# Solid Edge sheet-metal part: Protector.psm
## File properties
Title: Protector
Author: windows
Template: Iso Metric Sheet Metal.psm
Last saved by: windows
Revision: 4
Application: Solid Edge
Username: windows
Density: 2712,000 kg/m^3
Accuracy: 0,990
Material Thickness: 1,00 mm
Bend Radius: 1,00 mm
Relief Width: 1,00 mm
Relief Length: 0,00 mm
Neutral Factor: 0,330
Minimum Arc Length: 0,10 mm
Deviational Tolerance: 0,10 mm
Material: Aluminum, 3004
Face Style: Aluminum
Fill Style: ANSI38(Aluminum)
Virtual Style: ANSI38(Aluminum)
Grouping: Metals\Aluminium Alloys
LibraryName: Materials
Coef. of Thermal Exp: 2.3e-05
Thermal Conductivity: 170.0
Specific Heat: 920.0
Modulus of Elasticity: 68947570000.0
Poisson's Ratio: 0.33
Yield Stress: 68947570.0
Ultimate Stress: 179263682.0
Elongation: 0.0
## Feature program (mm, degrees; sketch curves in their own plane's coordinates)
base tab "unnamed BaseTab 1"
multi flange "Multi_Edge_Flange_1"  FlangeHeight = 3 mm; Angle = 90 deg
drawn cutout "DrawnCutout_1"
bead "Bead_1"
louver "Louver_1"  LouverDepth = 3 mm; LouverHeight = 2 mm
jog tab "JogTab_1"  OffsetDistance = 0.05 mm
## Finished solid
Body 1: solid body, 59 faces, 168 edges, 110 vertices.
  Faces by surface: plane 31, cylinder 14, blend 4, sphere 4, offset 2, spline 2, torus 2
  Edges by curve: line 92, circle 40, intersection 34, spline 2
Bounding box of the edges (mm; curved faces can reach further): 42.000 x 38.874 x 14.750, from (-16, 0, -3.75) to (26, 38.8744, 11).
Cylindrical faces by radius (mm): R1 x4, R2 x4, R2.25 x1, R3 x1, R3.25 x1, R4 x1, R8.18 x1, R9.18 x1
Toroidal faces (ring radius, tube radius in mm): R12.18 r3 x1, R12.18 r4 x1
Spherical faces by radius (mm): R2.25 x2, R3.25 x2
Planar faces by outward normal: +x 3, +y 5, +z 6, -x 3, -y 7, -z 7
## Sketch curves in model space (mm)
line (3, 0, 0) -> (3, 4, 0)
line (3, 4, 0) -> (7, 4, 0)
line (7, 4, 0) -> (7, 0, 0)
line (7, 0, 0) -> (10, 0, 0)
line (10, 0, 0) -> (10, 8.8744, 0)
line (10, 8.8744, 0) -> (26, 8.8744, 0)
line (26, 8.8744, 0) -> (26, 38.8744, 0)
line (-16, 38.8744, 0) -> (26, 38.8744, 0)
line (-16, 8.8744, 0) -> (-16, 38.8744, 0)
line (0, 8.8744, 0) -> (-16, 8.8744, 0)
line (0, 0, 0) -> (0, 8.8744, 0)
line (0, 0, 0) -> (3, 0, 0)
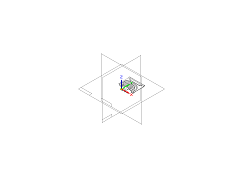
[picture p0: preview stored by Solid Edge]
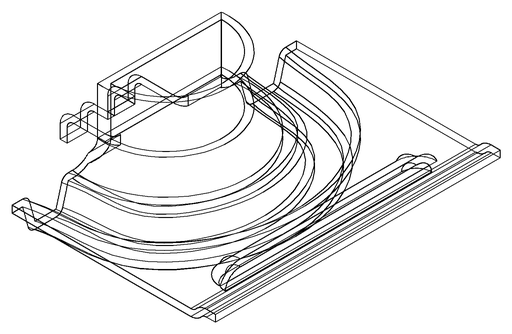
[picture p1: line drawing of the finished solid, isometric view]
